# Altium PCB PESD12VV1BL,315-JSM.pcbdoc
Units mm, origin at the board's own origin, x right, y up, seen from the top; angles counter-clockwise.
Board outline 14.28 x 13.5 mm, 2 copper layers (Top Layer, Bottom Layer), stack 0 mm thick; 1 components, 0 nets, 2 pads, 0 vias.
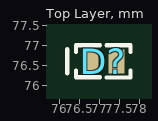
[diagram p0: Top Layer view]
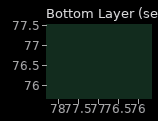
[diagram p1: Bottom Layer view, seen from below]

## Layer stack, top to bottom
Top Layer: signal copper (thickness not stored)
Bottom Layer: signal copper (thickness not stored)

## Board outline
84.135,69.85 69.85,69.85 69.85,83.35 84.135,83.35

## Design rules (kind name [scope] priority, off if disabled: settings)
PasteMaskExpansion "Paste Mask Expansion" [All] p1: expansion=0
SolderMaskExpansion "Solder Mask Expansion" [IsVia] p1: expansion=-25.4 istentingtop=TRUE
SolderMaskExpansion "Solder Mask Expansion" [All] p2: expansion=0.051 istentingtop=FALSE

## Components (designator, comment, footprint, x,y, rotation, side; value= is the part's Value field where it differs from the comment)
D? "PESD12VV1BL,315-JSM" DFN1006-2L-BI-1 77.1,76.6 r0 top

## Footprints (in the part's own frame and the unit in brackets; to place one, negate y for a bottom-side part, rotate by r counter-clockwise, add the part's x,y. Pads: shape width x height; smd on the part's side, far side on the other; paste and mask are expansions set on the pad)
DFN1006-2L-BI-1 [mm]
  rect 0.4x0.6 smd: 1(-0.325,0) 2(0.325,0)
  silkscreen extent -0.9,-0.4 0.68,0.4

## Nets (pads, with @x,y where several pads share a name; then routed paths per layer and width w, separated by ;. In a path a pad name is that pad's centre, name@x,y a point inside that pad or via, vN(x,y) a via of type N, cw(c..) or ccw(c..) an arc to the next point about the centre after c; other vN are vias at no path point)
pads on no net: D?.1 D?.2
